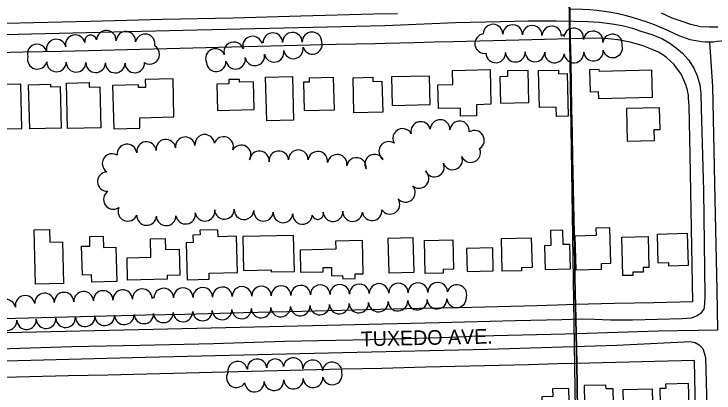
# Model space of a CAD drawing. Extents: x -25029 to 2274964, y -81170 to 687028.
# Drawn here: x -16875 to -16160, y -65597 to -65210 of the extents above; entities that cross this region are included whole.
import ezdxf

# ---------------------------------------------------------------- set-up
doc = ezdxf.new("R2010")
doc.units = 0
for name, color, linetype in [('81911BEA - RW_X_Fee_RW', 7, 'Continuous'), ('BLDG', 7, 'Continuous'), ('DIVISIONS', 7, 'Continuous'), ('DV_X_Corp_Line', 7, 'Continuous'), ('GE_X_CL_2000', 7, 'Continuous'), ('ROAD', 7, 'Continuous'), ('ROAD-NAME', 7, 'Continuous'), ('TREES', 7, 'Continuous')]:
    doc.layers.add(name, color=color, linetype=linetype)

msp = doc.modelspace()

# ---------------------------------------------------------------- linework, layer by layer
at = {"layer": '81911BEA - RW_X_Fee_RW'}
msp.add_line((-16284.17, -65234.45), (-16307.15, -65235.01), dxfattribs=at)
for points in [[(-16307.15, -65235.01), (-16346.3, -65236.22), (-16386.29, -65237.19), (-16426.28, -65238.17), (-16446.27, -65238.66), (-16466.27, -65239.14), (-16496.26, -65239.88), (-16506.26, -65240.12), (-16546.25, -65241.09), (-16586.24, -65242.07), (-16626.23, -65243.04), (-16666.21, -65244.02), (-16706.2, -65244.99), (-16746.19, -65245.97), (-16786.18, -65246.94), (-16826.17, -65247.92), (-16866.16, -65248.89), (-16906.15, -65249.87), (-16946.14, -65250.85), (-16986.13, -65251.82), (-17026.12, -65252.8), (-17066.11, -65253.77), (-17106.09, -65254.75), (-17146.08, -65255.72)], [(-16221.68, -65246.63), (-16233.66, -65242.04), (-16245.99, -65238.51), (-16258.58, -65236.05), (-16271.34, -65234.7), (-16284.17, -65234.45)], [(-16185.82, -65300.1), (-16186.16, -65294.88), (-16186.23, -65292.5), (-16186.97, -65289.72), (-16187.46, -65287.49), (-16188.21, -65284.64), (-16188.83, -65282.66), (-16189.89, -65279.69), (-16190.6, -65277.96), (-16192, -65274.91), (-16192.76, -65273.43), (-16194.52, -65270.32), (-16195.29, -65269.09), (-16197.43, -65265.98), (-16198.18, -65264.99), (-16200.71, -65261.91), (-16201.4, -65261.14), (-16204.33, -65258.14), (-16204.94, -65257.57), (-16208.52, -65254.51), (-16212.67, -65251.51), (-16217.07, -65248.87), (-16221.68, -65246.63)], [(-16181.78, -65503.57), (-16184.76, -65353.6), (-16185.75, -65303.61), (-16185.82, -65300.1)], [(-16320.66, -65506.96), (-16340.97, -65507.71), (-16380.96, -65508.68), (-16420.95, -65509.66), (-16460.94, -65510.63), (-16500.93, -65511.61), (-16580.9, -65513.56), (-16640.89, -65515.02), (-16700.87, -65516.48), (-16740.86, -65517.46), (-16765.85, -65518.07), (-16780.85, -65518.43), (-16820.84, -65519.41), (-16860.83, -65520.38), (-16900.82, -65521.36), (-16950.8, -65522.58), (-17000.79, -65523.79), (-17050.78, -65525.01), (-17100.76, -65526.23), (-17115.76, -65526.6)], [(-16181.78, -65503.57), (-16221.76, -65504.55), (-16261.75, -65505.53), (-16301.73, -65506.5), (-16320.66, -65506.96)], [(-16180.58, -65563.56), (-16220.57, -65564.54), (-16260.56, -65565.51), (-16300.53, -65566.49), (-16319.97, -65566.97)], [(-16180.58, -65563.56), (-16178.19, -65683.53), (-16177.53, -65717.01)], [(-16319.97, -65566.97), (-16349.78, -65567.94), (-16409.76, -65569.4), (-16454.75, -65570.5), (-16499.73, -65571.6), (-16539.72, -65572.57), (-16579.71, -65573.55), (-16619.7, -65574.52), (-16659.69, -65575.5), (-16699.68, -65576.47), (-16739.67, -65577.45), (-16779.66, -65578.42), (-16819.65, -65579.4), (-16859.64, -65580.37), (-16899.63, -65581.35), (-16949.61, -65582.57), (-16999.6, -65583.78), (-17049.58, -65585), (-17099.57, -65586.22)]]:
    msp.add_lwpolyline(points, dxfattribs=at)
at = {"layer": 'BLDG'}
for points in [[(-16388.18, -65302.01), (-16403.08, -65302.37), (-16402.8, -65313.87), (-16419.19, -65314.27), (-16419.39, -65305.87), (-16441.72, -65306.41), (-16442.31, -65282.07), (-16426.96, -65281.7), (-16427.3, -65267.44), (-16389.04, -65266.52)], [(-16371.29, -65267.98), (-16371.16, -65273.65), (-16379.2, -65273.84), (-16378.55, -65300.79), (-16349.36, -65300.09), (-16350.15, -65267.47)], [(-16319.09, -65267.1), (-16319, -65270.92), (-16310.26, -65270.71), (-16309.21, -65314.26), (-16321.22, -65314.55), (-16321.45, -65304.93), (-16338.63, -65305.34), (-16339.54, -65267.59)], [(-16223.89, -65267.16), (-16277.41, -65268.45), (-16277.46, -65266.52), (-16287.35, -65266.75), (-16286.82, -65289.09), (-16278.6, -65288.89), (-16278.43, -65296.11), (-16223.23, -65294.78)], [(-16798.73, -65279.89), (-16798.62, -65284.5), (-16787.8, -65284.24), (-16786.8, -65326.03), (-16820.84, -65326.85), (-16821.96, -65280.45)], [(-16741.48, -65276.76), (-16741.29, -65284.73), (-16748.22, -65284.9), (-16748.29, -65282.25), (-16774.7, -65282.89), (-16773.64, -65327), (-16746.77, -65326.35), (-16747.03, -65315.69), (-16712.08, -65314.85), (-16713.02, -65276.07)], [(-16630.83, -65279.01), (-16645.18, -65279.35), (-16645.25, -65276.52), (-16656.02, -65276.77), (-16655.91, -65281.24), (-16668.22, -65281.54), (-16667.57, -65308.37), (-16630.15, -65307.46)], [(-16590.91, -65273.51), (-16589.83, -65318.24), (-16617.28, -65318.9), (-16618.36, -65274.18)], [(-16573.97, -65275.36), (-16573.88, -65279.35), (-16579.8, -65279.5), (-16579.11, -65308.32), (-16548.18, -65307.57), (-16548.97, -65274.75)], [(-16508.86, -65274.34), (-16508.75, -65278.72), (-16499.55, -65278.5), (-16498.79, -65310.05), (-16528.15, -65310.76), (-16529.02, -65274.83)], [(-16489, -65303.06), (-16450.15, -65302.12), (-16450.85, -65273.11), (-16489.7, -65274.05)], [(-16888.54, -65281.84), (-16888.41, -65286.9), (-16899.54, -65287.17), (-16898.57, -65327.47), (-16867.54, -65326.72), (-16868.63, -65281.36)], [(-16838.34, -65281.58), (-16838.27, -65284.19), (-16828.44, -65283.95), (-16827.42, -65326.23), (-16859.43, -65327), (-16860.51, -65282.12)], [(-16221.16, -65338.9), (-16221.43, -65327.73), (-16215.31, -65327.59), (-16215.85, -65305.43), (-16249.62, -65306.24), (-16248.81, -65339.57)], [(-16839.32, -65429.87), (-16839.02, -65442.72), (-16825.83, -65442.4), (-16824.81, -65484.88), (-16853.6, -65485.57), (-16854.94, -65430.25)], [(-16666.9, -65437.15), (-16667.07, -65430.18), (-16685.45, -65430.62), (-16685.34, -65435.44), (-16692.74, -65435.62), (-16692.56, -65443.21), (-16699.48, -65443.38), (-16698.56, -65481.22), (-16675.98, -65480.68), (-16676.14, -65474.32), (-16647.19, -65473.63), (-16648.08, -65436.69)], [(-16280.86, -65428.41), (-16280.67, -65436.04), (-16302.32, -65436.56), (-16301.49, -65471.02), (-16275.13, -65470.38), (-16275.27, -65464.45), (-16265.74, -65464.22), (-16266.61, -65428.06)], [(-16797.88, -65446.78), (-16798.12, -65437.08), (-16784.35, -65436.75), (-16784.08, -65448.08), (-16771.32, -65447.77), (-16770.47, -65483.08), (-16796.11, -65483.7), (-16796.3, -65476.19), (-16805.65, -65476.42), (-16806.36, -65446.99)], [(-16640.99, -65471.76), (-16612.75, -65471.08), (-16612.7, -65473.21), (-16588.92, -65472.63), (-16589.8, -65435.85), (-16641.82, -65437.1)], [(-16307.03, -65470.06), (-16307.63, -65445.09), (-16314.47, -65445.26), (-16314.83, -65430.67), (-16327.31, -65430.97), (-16326.94, -65446.32), (-16333.44, -65446.47), (-16332.85, -65470.68)], [(-16227.6, -65436.85), (-16226.84, -65468.53), (-16232.69, -65468.67), (-16232.58, -65473.24), (-16243.26, -65473.5), (-16243.18, -65476.69), (-16253.57, -65476.94), (-16254.52, -65437.5)], [(-16217.53, -65463.91), (-16206.89, -65463.65), (-16206.81, -65466.77), (-16186.41, -65466.28), (-16187.19, -65434.04), (-16218.24, -65434.79)], [(-16760.02, -65458.79), (-16735.66, -65458.2), (-16736.11, -65439.29), (-16721.08, -65438.93), (-16720.81, -65450.1), (-16706.62, -65449.76), (-16705.97, -65476.54), (-16719, -65476.85), (-16718.91, -65480.51), (-16759.47, -65481.49)], [(-16546.89, -65441.69), (-16546.69, -65449.94), (-16583.16, -65450.82), (-16582.61, -65473.53), (-16559.65, -65472.98), (-16559.75, -65468.79), (-16551.14, -65468.58), (-16550.93, -65477.13), (-16539.69, -65476.86), (-16539.61, -65480.1), (-16526.8, -65479.79), (-16526.91, -65475.22), (-16518.56, -65475.02), (-16519.38, -65441.02)], [(-16493.43, -65438.89), (-16492.58, -65474.01), (-16466.68, -65473.39), (-16467.53, -65438.26)], [(-16427.14, -65440.44), (-16426.42, -65470.27), (-16437.05, -65470.53), (-16436.96, -65474.29), (-16455.23, -65474.73), (-16456.04, -65441.14)], [(-16346.92, -65438.41), (-16346.2, -65468.59), (-16356.99, -65468.85), (-16356.91, -65472.05), (-16376.71, -65472.52), (-16377.51, -65439.15)], [(-16412.42, -65472.77), (-16385.75, -65472.13), (-16386.32, -65448.44), (-16412.99, -65449.08)], [(-16209.68, -65587.6), (-16209.57, -65592.08), (-16215.57, -65592.22), (-16214.87, -65621.31), (-16185.38, -65620.6), (-16186.19, -65587.04)], [(-16319.93, -65636.6), (-16320.05, -65631.57), (-16307.51, -65631.26), (-16308.45, -65592.19), (-16325.28, -65592.59), (-16325.09, -65600.45), (-16336.26, -65600.72), (-16335.39, -65636.97)], [(-16262.56, -65622.89), (-16263.29, -65592.48), (-16270.55, -65592.66), (-16270.64, -65588.66), (-16293, -65589.2), (-16292.17, -65623.6)], [(-16253.18, -65593.15), (-16223.33, -65592.43), (-16222.63, -65621.69), (-16252.48, -65622.41)]]:
    msp.add_lwpolyline(points, close=True, dxfattribs=at)
at = {"layer": 'DIVISIONS'}
msp.add_line((-16252.4, -68748.36), (-16315.19, -64748.36), dxfattribs=at)
msp.add_line((-16252.4, -68748.36), (-16315.19, -64748.36), dxfattribs=at)
at = {"layer": 'DV_X_Corp_Line'}
for p, q in [((-16307.15, -65235.01), (-16308.34, -65175.03)), ((-16307.15, -65235.01), (-16308.34, -65175.03)), ((-16308.34, -65175.03), (-16307.15, -65235.01)), ((-16308.34, -65175.03), (-16307.15, -65235.01)), ((-16306.68, -65257.98), (-16307.15, -65235.01)), ((-16306.68, -65257.98), (-16307.15, -65235.01)), ((-16307.15, -65235.01), (-16306.68, -65257.98)), ((-16307.15, -65235.01), (-16306.68, -65257.98)), ((-16305.72, -65306.54), (-16306.68, -65257.98)), ((-16305.72, -65306.54), (-16306.68, -65257.98)), ((-16306.68, -65257.98), (-16305.72, -65306.54)), ((-16306.68, -65257.98), (-16305.72, -65306.54)), ((-16305.22, -65331.54), (-16305.72, -65306.54)), ((-16305.22, -65331.54), (-16305.72, -65306.54)), ((-16305.72, -65306.54), (-16305.22, -65331.54)), ((-16305.72, -65306.54), (-16305.22, -65331.54)), ((-16304.73, -65356.53), (-16305.22, -65331.54)), ((-16304.73, -65356.53), (-16305.22, -65331.54)), ((-16305.22, -65331.54), (-16304.73, -65356.53)), ((-16305.22, -65331.54), (-16304.73, -65356.53)), ((-16304.72, -65356.78), (-16304.73, -65356.53)), ((-16304.72, -65356.78), (-16304.73, -65356.53)), ((-16304.73, -65356.53), (-16304.72, -65356.78)), ((-16304.73, -65356.53), (-16304.72, -65356.78)), ((-16304.13, -65386.24), (-16304.72, -65356.78)), ((-16304.13, -65386.24), (-16304.72, -65356.78)), ((-16304.72, -65356.78), (-16304.13, -65386.24)), ((-16304.72, -65356.78), (-16304.13, -65386.24)), ((-16303.73, -65406.23), (-16304.13, -65386.24)), ((-16303.73, -65406.23), (-16304.13, -65386.24)), ((-16304.13, -65386.24), (-16303.73, -65406.23)), ((-16304.13, -65386.24), (-16303.73, -65406.23)), ((-16303.53, -65416.23), (-16303.73, -65406.23)), ((-16303.53, -65416.23), (-16303.73, -65406.23)), ((-16303.73, -65406.23), (-16303.53, -65416.23)), ((-16303.73, -65406.23), (-16303.53, -65416.23)), ((-16303.13, -65436.22), (-16303.53, -65416.23)), ((-16303.13, -65436.22), (-16303.53, -65416.23)), ((-16303.53, -65416.23), (-16303.13, -65436.22)), ((-16303.53, -65416.23), (-16303.13, -65436.22)), ((-16302.93, -65446.22), (-16303.13, -65436.22)), ((-16302.93, -65446.22), (-16303.13, -65436.22)), ((-16303.13, -65436.22), (-16302.93, -65446.22)), ((-16303.13, -65436.22), (-16302.93, -65446.22)), ((-16302.53, -65466.22), (-16302.93, -65446.22)), ((-16302.53, -65466.22), (-16302.93, -65446.22)), ((-16302.93, -65446.22), (-16302.53, -65466.22)), ((-16302.93, -65446.22), (-16302.53, -65466.22)), ((-16302.33, -65476.22), (-16302.53, -65466.22)), ((-16302.33, -65476.22), (-16302.53, -65466.22)), ((-16302.53, -65466.22), (-16302.33, -65476.22)), ((-16302.53, -65466.22), (-16302.33, -65476.22)), ((-16301.94, -65496.21), (-16302.33, -65476.22)), ((-16301.94, -65496.21), (-16302.33, -65476.22)), ((-16302.33, -65476.22), (-16301.94, -65496.21)), ((-16302.33, -65476.22), (-16301.94, -65496.21)), ((-16301.73, -65506.5), (-16301.94, -65496.21)), ((-16301.73, -65506.5), (-16301.94, -65496.21)), ((-16301.94, -65496.21), (-16301.73, -65506.5)), ((-16301.94, -65496.21), (-16301.73, -65506.5)), ((-16300.53, -65566.49), (-16301.73, -65506.5)), ((-16300.53, -65566.49), (-16301.73, -65506.5)), ((-16301.73, -65506.5), (-16300.53, -65566.49)), ((-16301.73, -65506.5), (-16300.53, -65566.49)), ((-16298.31, -65678.09), (-16300.53, -65566.49)), ((-16298.31, -65678.09), (-16300.53, -65566.49)), ((-16300.53, -65566.49), (-16298.31, -65678.09)), ((-16300.53, -65566.49), (-16298.31, -65678.09))]:
    msp.add_line(p, q, dxfattribs=at)
at = {"layer": 'GE_X_CL_2000'}
for points in [[(-15874.84, -65110.19), (-15905.47, -65124.29), (-15925.1, -65133.14), (-15944.64, -65142.18), (-15964.09, -65151.42), (-15983.44, -65160.86), (-16002.7, -65170.49), (-16024.7, -65181.12), (-16046.79, -65191.55), (-16068.97, -65201.8), (-16091.24, -65211.85), (-16101.06, -65216.77), (-16110.99, -65221.49), (-16121.01, -65226), (-16131.12, -65230.29), (-16141.32, -65234.37), (-16145.13, -65235.6), (-16149, -65236.62), (-16152.92, -65237.42), (-16156.88, -65238.02), (-16160.87, -65238.39), (-16164.87, -65238.54)], [(-16164.87, -65238.54), (-16168.87, -65238.48), (-16172.86, -65238.19), (-16176.83, -65237.69), (-16180.77, -65236.97), (-16184.66, -65236.04), (-16188.5, -65234.89), (-16192.26, -65233.54), (-16195.95, -65231.98), (-16206.66, -65226.95), (-16213.87, -65223.86), (-16221.15, -65220.98), (-16228.51, -65218.29), (-16235.94, -65215.81), (-16243.43, -65213.53), (-16250.99, -65211.45), (-16258.14, -65209.77), (-16265.34, -65208.34), (-16272.59, -65207.15), (-16279.87, -65206.2), (-16287.18, -65205.5), (-16294.51, -65205.04), (-16306.72, -65204.86)], [(-16483.49, -65209.48), (-16508.21, -65209.98), (-16582.54, -65211.95), (-16651.42, -65213.95), (-16723.42, -65215.28), (-16797.25, -65217.42), (-16884.04, -65219.5), (-16957.52, -65221.15), (-17111.97, -65225.24), (-17197.84, -65227.32), (-17276.01, -65229.61), (-17354.02, -65231.08), (-17504.87, -65234.85), (-17570.86, -65236.05), (-17619.36, -65237.43)], [(-16164.87, -65238.54), (-16161.72, -65283.83), (-16159.53, -65399.22), (-16157.36, -65491.59), (-16156.69, -65532.61)], [(-16300.11, -65536.25), (-16312.39, -65536.65), (-16399.86, -65538.63), (-16438.71, -65540.34), (-16511.86, -65542.49), (-16599.15, -65544.25), (-16671.8, -65546.55), (-16746.48, -65548.19), (-16816.48, -65549.7), (-16880.21, -65551.55), (-16960.88, -65552.85), (-17028.9, -65554.52), (-17100.7, -65556.5), (-17177.33, -65558.79), (-17250.81, -65560.12), (-17324.27, -65562.1), (-17389.54, -65563.46), (-17459.18, -65565.77), (-17536.41, -65566.6), (-17627.71, -65569.48)], [(-16156.69, -65532.61), (-16217.24, -65533.52), (-16300.11, -65536.25)]]:
    msp.add_lwpolyline(points, dxfattribs=at)
at = {"layer": 'ROAD'}
for points in [[(-16156.26, -65223.13), (-16165.05, -65223.28), (-16174.13, -65222.78), (-16184.08, -65220.36), (-16192.77, -65217.51), (-16202.93, -65213.92), (-16213.95, -65208.93)], [(-16942.24, -65232.13), (-16702.91, -65226.28), (-16496.69, -65221.5), (-16424.45, -65218.37), (-16378.37, -65217.54), (-16350.46, -65216.79), (-16321.31, -65216.86), (-16302.93, -65216.99), (-16288.87, -65217.54), (-16277.15, -65218.21), (-16264.35, -65219.77), (-16254.18, -65221.6), (-16243.43, -65224.17), (-16235.03, -65227.16), (-16223.85, -65230.76), (-16213.63, -65234.94), (-16205.31, -65239.69), (-16198.54, -65244.57), (-16192.57, -65249.89), (-16186.32, -65256.6), (-16180.89, -65264.99), (-16177.36, -65272.92), (-16174.57, -65282.17), (-16173.76, -65290.9), (-16173.36, -65306.13), (-16171.12, -65390.45), (-16169.78, -65497.18), (-16169.92, -65505.75), (-16170.77, -65511.24), (-16173.95, -65515.46), (-16177.48, -65518.07), (-16183.65, -65520.22), (-16192.59, -65521.11), (-16243.36, -65522.27), (-16255.15, -65522.55), (-16265.85, -65522.4), (-16282.39, -65521.84), (-16296.09, -65521.45), (-16315.65, -65522.18), (-16362.97, -65522.93), (-16441.21, -65524.99), (-16556.01, -65527.88), (-16688.82, -65531.08), (-16882.44, -65535.21)], [(-17660.42, -65583.01), (-17581.53, -65581.11), (-17380.36, -65575.64), (-17212.96, -65571.01), (-17089.38, -65568.77), (-16897.89, -65564.18), (-16741.55, -65560.13), (-16539.88, -65555.32), (-16391.68, -65552.09), (-16259.66, -65548.08), (-16190.86, -65544.49), (-16185.07, -65544.16), (-16179.66, -65545.23), (-16175.43, -65547.75), (-16171.79, -65551.44), (-16170.14, -65555.63), (-16169.01, -65560.69), (-16167.12, -65623.33)]]:
    msp.add_lwpolyline(points, dxfattribs=at)
at = {"layer": 'TREES'}
for centre, radius, start, end in [((-16386.04, -65230.31), 10, 359.10233, 179.10233), ((-16366.04, -65230.81), 10, 358.05364, 178.05364), ((-16346.06, -65231.48), 10, 358.05364, 178.05364), ((-16326.07, -65232.16), 10, 358.05364, 178.05364), ((-16781.19, -65236.63), 10, 356.97401, 176.97401), ((-16761.21, -65237.69), 10, 356.97401, 176.97401), ((-16610.98, -65239.06), 10, 1.17655, 181.17655), ((-16590.98, -65238.65), 10, 1.17655, 181.17655), ((-16570.99, -65238.24), 10, 1.17655, 181.17655), ((-16303.49, -65234.14), 10, 351.12357, 171.12357), ((-16283.73, -65237.22), 10, 351.12357, 171.12357), ((-16832.4, -65245.55), 10, 12.90649, 192.90649), ((-16812.9, -65241.08), 10, 12.90649, 192.90649), ((-16797.16, -65237.48), 6.15, 12.90649, 192.90649), ((-16741.44, -65240.29), 10, 348.02956, 168.02956), ((-16631.83, -65242.56), 10, 16.9165, 196.9165), ((-16394.61, -65240.05), 10, 98.20239, 278.20239), ((-16314.72, -65232.55), 1.35, 358.05364, 178.05364), ((-16263.97, -65240.31), 10, 351.12357, 171.12357), ((-16851.74, -65250.6), 10, 16.35532, 196.35532), ((-16736.86, -65250.91), 10, 238.70636, 58.70636), ((-16650.96, -65248.38), 10, 16.9165, 196.9165), ((-16621.62, -65239.46), 0.672, 16.9165, 196.9165), ((-16590.03, -65245.4), 10, 190.1934, 10.1934), ((-16570.59, -65240.83), 10, 196.26176, 16.26176), ((-16263.77, -65244.35), 10, 194.46549, 14.46549), ((-16669.7, -65255.28), 10, 23.50924, 203.50924), ((-16629.4, -65252.48), 10, 190.1934, 10.1934), ((-16609.71, -65248.94), 10, 190.1934, 10.1934), ((-16383.19, -65249.56), 10, 182.23886, 2.23886), ((-16363.21, -65248.78), 10, 182.23886, 2.23886), ((-16343.22, -65248.56), 10, 179.01462, 359.01462), ((-16323.25, -65249.6), 10, 174.98584, 354.98584), ((-16303.33, -65249.57), 10, 185.20341, 5.20341), ((-16283.42, -65247.76), 10, 185.20341, 5.20341), ((-16851.68, -65256.02), 10, 164.87708, 344.87708), ((-16832.03, -65258.81), 10, 178.96993, 358.96993), ((-16668.9, -65258.53), 10, 184.24906, 4.24906), ((-16649.08, -65256.02), 10, 190.1934, 10.1934), ((-16812.03, -65259.17), 10, 178.96993, 358.96993), ((-16792.04, -65259.53), 10, 178.96993, 358.96993), ((-16772.04, -65259.89), 10, 178.96993, 358.96993), ((-16752.05, -65259.76), 10, 181.77176, 1.77176), ((-16459.87, -65329.73), 10, 13.2479, 193.2479), ((-16440.14, -65327.74), 10, 358.23796, 178.23796), ((-16420.2, -65329.12), 10, 353.84023, 173.84023), ((-16478.36, -65336.85), 10, 28.90674, 208.90674), ((-16404.98, -65338.69), 10, 301.88979, 121.88979), ((-16700.48, -65345.34), 10, 7.02888, 187.02888), ((-16680.63, -65342.89), 10, 7.06099, 187.06099), ((-16661.32, -65345.1), 10, 339.8779, 159.8779), ((-16760.02, -65352.73), 10, 7.29494, 187.29494), ((-16740.18, -65350.23), 10, 7.02888, 187.02888), ((-16720.33, -65347.79), 10, 7.02888, 187.02888), ((-16643.34, -65353.67), 10, 329.1247, 149.1247), ((-16492.66, -65350), 10, 56.30061, 236.30061), ((-16624.8, -65359.73), 10, 354.67806, 174.67806), ((-16604.9, -65359.63), 10, 5.89981, 185.89981), ((-16584.95, -65358.59), 10, 0.04895, 180.04895), ((-16565.06, -65360.07), 10, 351.44763, 171.44763), ((-16408.8, -65351.31), 10, 204.43488, 24.43488), ((-16775.31, -65362.43), 10, 57.51396, 237.51396), ((-16545.31, -65363.21), 10, 350.49328, 170.49328), ((-16525.57, -65366.44), 10, 350.89689, 170.89689), ((-16506.96, -65363.17), 10, 29.01117, 209.01117), ((-16427.33, -65358.8), 10, 199.58072, 19.58072), ((-16445.94, -65366.08), 10, 203.16007, 23.16007), ((-16780.12, -65380.85), 10, 93.21264, 273.21264), ((-16461.63, -65377.63), 10, 229.53938, 49.53938), ((-16475.53, -65391.95), 10, 222.17909, 42.17909), ((-16774.01, -65399.16), 10, 123.68715, 303.68715), ((-16491.31, -65404.12), 10, 213.08893, 33.08893), ((-16759.22, -65411.27), 10, 157.69338, 337.69338), ((-16739.98, -65415.58), 10, 177.06598, 357.06598), ((-16719.99, -65415.9), 10, 181.09943, 1.09943), ((-16700.11, -65414.22), 10, 188.53963, 8.53963), ((-16680.33, -65411.25), 10, 188.53963, 8.53963), ((-16660.45, -65409.34), 10, 182.44574, 2.44574), ((-16640.49, -65409.71), 10, 175.44134, 355.44134), ((-16620.55, -65411.3), 10, 175.44134, 355.44134), ((-16600.61, -65412.89), 10, 175.44134, 355.44134), ((-16580.68, -65414.48), 10, 175.44134, 355.44134), ((-16565.11, -65413.71), 5.81, 195.58308, 15.58308), ((-16549.52, -65411.65), 10, 182.85964, 2.85964), ((-16529.54, -65411.56), 10, 177.67051, 357.67051), ((-16509.62, -65410.77), 10, 186.83951, 6.83951), ((-16602.57, -65497.27), 10, 1.2314, 181.2314), ((-16582.58, -65496.84), 10, 1.2314, 181.2314), ((-16562.58, -65496.41), 10, 1.2314, 181.2314), ((-16542.59, -65495.98), 10, 1.2314, 181.2314), ((-16522.59, -65495.56), 10, 1.2314, 181.2314), ((-16502.6, -65495.13), 10, 1.2314, 181.2314), ((-16482.6, -65494.7), 10, 1.2314, 181.2314), ((-16462.61, -65494.27), 10, 1.2314, 181.2314), ((-16442.61, -65493.84), 10, 1.2314, 181.2314), ((-16422.95, -65496.19), 10, 345.12548, 165.12548), ((-16824.32, -65503.99), 10, 2.44689, 182.44689), ((-16804.34, -65503.14), 10, 2.44689, 182.44689), ((-16784.36, -65502.28), 10, 2.44689, 182.44689), ((-16764.37, -65501.43), 10, 2.44689, 182.44689), ((-16744.39, -65500.57), 10, 2.44689, 182.44689), ((-16722.55, -65499.85), 10, 1.2314, 181.2314), ((-16702.55, -65499.42), 10, 1.2314, 181.2314), ((-16682.56, -65498.99), 10, 1.2314, 181.2314), ((-16662.56, -65498.56), 10, 1.2314, 181.2314), ((-16642.57, -65498.13), 10, 1.2314, 181.2314), ((-16622.57, -65497.7), 10, 1.2314, 181.2314), ((-16883.68, -65511.3), 10, 12.42868, 192.42868), ((-16864.1, -65507.21), 10, 11.17898, 191.17898), ((-16844.3, -65504.84), 10, 2.44689, 182.44689), ((-16733.47, -65500.11), 0.929, 2.44689, 182.44689), ((-16463.17, -65501.97), 10, 182.8664, 2.8664), ((-16443.2, -65500.97), 10, 182.8664, 2.8664), ((-16423.25, -65499.61), 10, 184.91492, 4.91492), ((-16603, -65508.97), 10, 182.8664, 2.8664), ((-16583.02, -65507.97), 10, 182.8664, 2.8664), ((-16563.05, -65506.97), 10, 182.8664, 2.8664), ((-16543.07, -65505.97), 10, 182.8664, 2.8664), ((-16523.1, -65504.97), 10, 182.8664, 2.8664), ((-16503.12, -65503.97), 10, 182.8664, 2.8664), ((-16483.15, -65502.97), 10, 182.8664, 2.8664), ((-16742.82, -65515.97), 10, 182.8664, 2.8664), ((-16722.85, -65514.97), 10, 182.8664, 2.8664), ((-16702.87, -65513.97), 10, 182.8664, 2.8664), ((-16682.9, -65512.97), 10, 182.8664, 2.8664), ((-16662.92, -65511.97), 10, 182.8664, 2.8664), ((-16642.95, -65510.97), 10, 182.8664, 2.8664), ((-16622.97, -65509.97), 10, 182.8664, 2.8664), ((-16882.65, -65522.97), 10, 182.8664, 2.8664), ((-16862.67, -65521.97), 10, 182.8664, 2.8664), ((-16842.7, -65520.97), 10, 182.8664, 2.8664), ((-16822.72, -65519.97), 10, 182.8664, 2.8664), ((-16802.75, -65518.97), 10, 182.8664, 2.8664), ((-16782.77, -65517.97), 10, 182.8664, 2.8664), ((-16762.8, -65516.97), 10, 182.8664, 2.8664), ((-16646.95, -65574.41), 10, 8.68601, 188.68601), ((-16627.1, -65572.07), 10, 4.75941, 184.75941), ((-16608.63, -65570.53), 8.54, 4.75941, 184.75941), ((-16590.18, -65570.9), 10, 353.83348, 173.83348), ((-16570.29, -65573.04), 10, 353.83348, 173.83348), ((-16550.41, -65575.19), 10, 353.83348, 173.83348), ((-16648.32, -65581.15), 10, 148.42532, 328.42532), ((-16569.99, -65581.23), 10, 184.22711, 4.22711), ((-16550.24, -65578.38), 10, 192.20081, 12.20081), ((-16629.83, -65585.65), 10, 184.22711, 4.22711), ((-16609.88, -65584.18), 10, 184.22711, 4.22711), ((-16589.93, -65582.7), 10, 184.22711, 4.22711)]:
    msp.add_arc(centre, radius, start, end, dxfattribs=at)

# ---------------------------------------------------------------- texts
at = {"layer": 'ROAD-NAME'}
msp.add_text('TUXEDO AVE.', height=15, rotation=1.19807, dxfattribs=at).set_placement((-16521.07, -65549.1))

doc.saveas('drawing.dxf')
